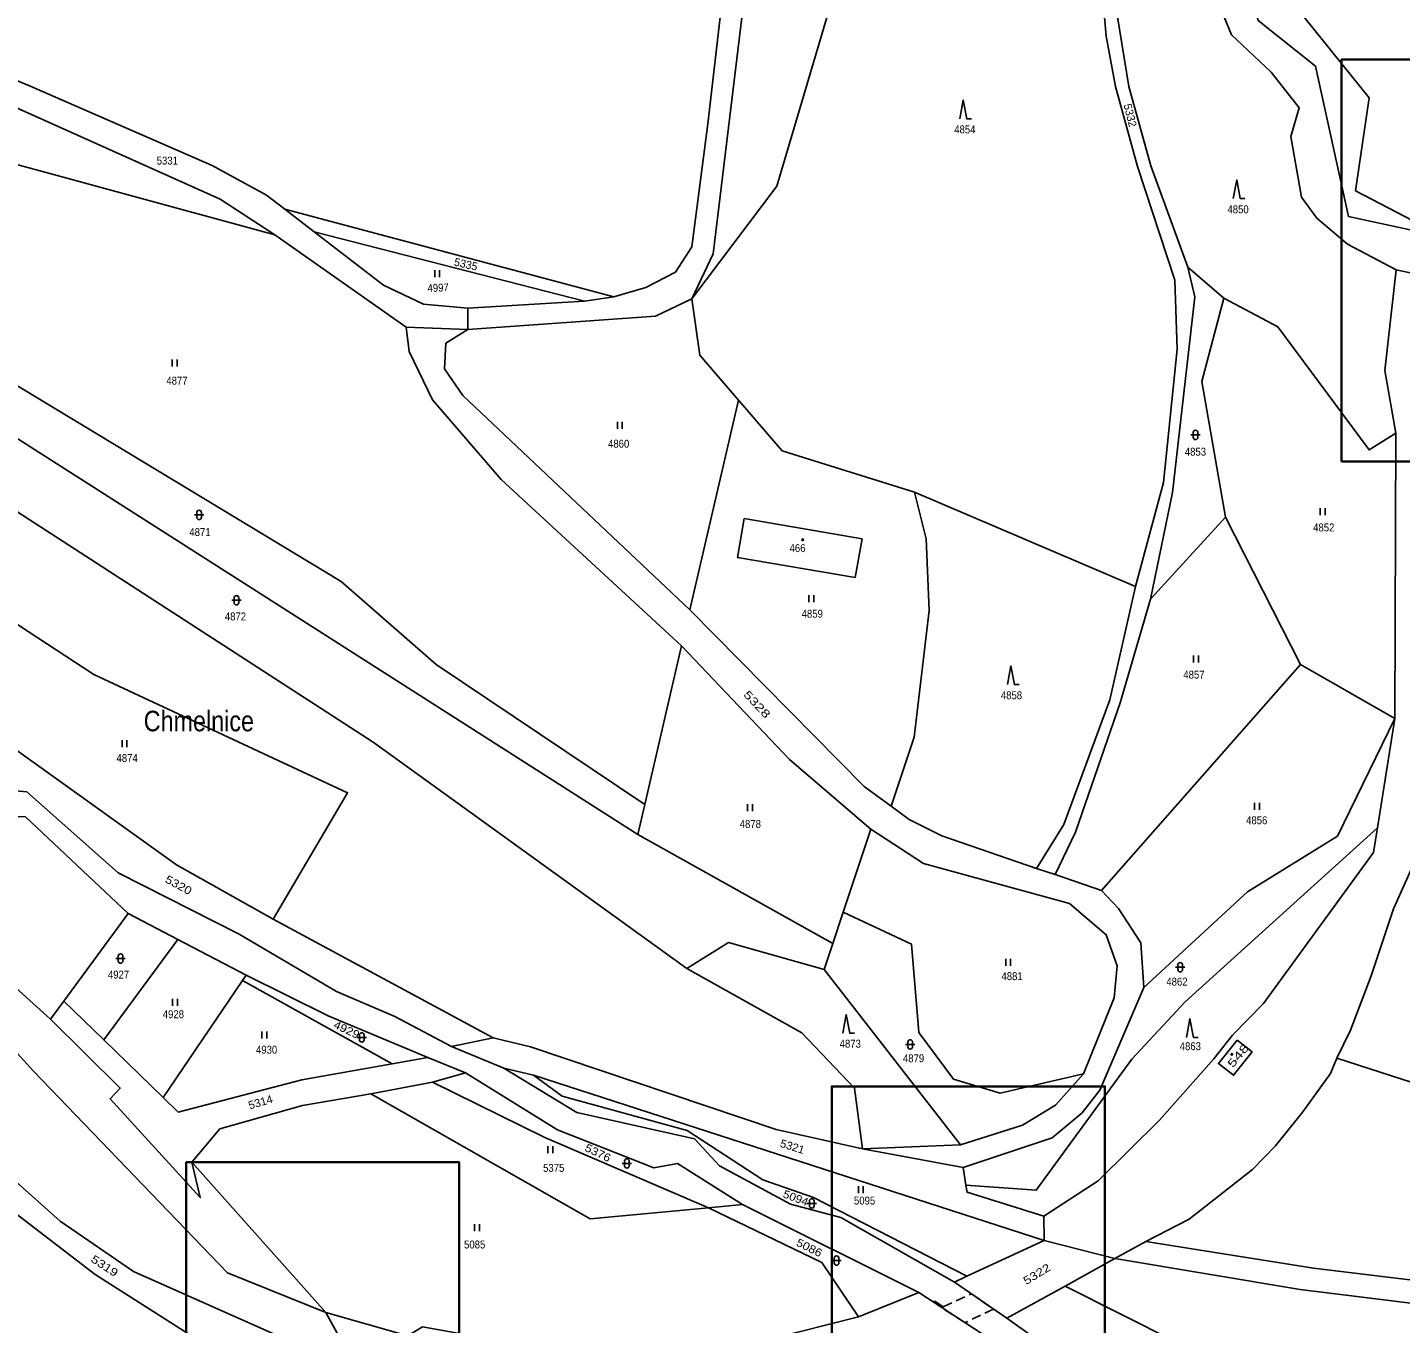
# Model space of a CAD drawing. Extents: x -665688 to -664583, y -1006118 to -1004927.
# Drawn here: x -665191.6 to -664897.5, y -1005454.1 to -1005176.4 of the extents above; entities that cross this region are included whole.
import ezdxf
from ezdxf.enums import TextEntityAlignment as Align

# ---------------------------------------------------------------- set-up
doc = ezdxf.new("R2010")
doc.units = 0
doc.header["$LTSCALE"] = 0.68
doc.linetypes.add('MEDIUM_DASHED', pattern=[4.5, 3, -1.5])
for name, color, linetype, lineweight in [('1', 7, 'Continuous', 25), ('25', 7, 'Continuous', 25), ('27', 7, 'MEDIUM_DASHED', 25), ('55', 7, 'Continuous', 35)]:
    doc.layers.add(name, color=color, linetype=linetype, lineweight=lineweight)
for name, color, linetype in [('15', 7, 'Continuous'), ('18', 7, 'Continuous'), ('19', 7, 'Continuous')]:
    doc.layers.add(name, color=color, linetype=linetype)

msp = doc.modelspace()

# ---------------------------------------------------------------- linework, layer by layer
at = {"layer": '1'}
for p, q in [((-665097.3, -1005241.05), (-665097.26, -1005236.54)), ((-665072.31, -1005234.98), (-665097.26, -1005236.54)), ((-665097.3, -1005241.05), (-665110.5, -1005240.56)), ((-664898.65, -1005324.46), (-664898.46, -1005263.33)), ((-664918.88, -1005312.89), (-664898.65, -1005324.46)), ((-664898.65, -1005324.46), (-664902.37, -1005347.86)), ((-664971.46, -1005357.88), (-664975.48, -1005356.59)), ((-665170.08, -1005366.25), (-665159.4, -1005371.83)), ((-665159.4, -1005371.83), (-665144.78, -1005379.46)), ((-665019.11, -1005372.67), (-665020.96, -1005378.24)), ((-665091.86, -1005392.84), (-665100.81, -1005394.75)), ((-665089.55, -1005399.37), (-665100.81, -1005394.75)), ((-665105.89, -1005397.05), (-665097.79, -1005400.37)), ((-665089.55, -1005399.37), (-665083.2, -1005400.84)), ((-665118.08, -1005404.88), (-665104.85, -1005402.34)), ((-664991.18, -1005420.63), (-665012.73, -1005416.63)), ((-665038.41, -1005428.56), (-665000.67, -1005447.45)), ((-664969.3, -1005446.1), (-664958.68, -1005440.16)), ((-664981.8, -1005452.97), (-664993.04, -1005445.2)), ((-664981.8, -1005452.97), (-664969.3, -1005446.1)), ((-665000.67, -1005447.45), (-665013.61, -1005452.67)), ((-665000.67, -1005447.45), (-664985.67, -1005457.24))]:
    msp.add_line(p, q, dxfattribs=at)
for points in [[(-664895.39, -1005219.73), (-664908.63, -1005216.84), (-664915.67, -1005184.63), (-664927.97, -1005174.84), (-664931.29, -1005161.96), (-664923.13, -1005157.75), (-664909.4, -1005145.58), (-664903.94, -1005133.92), (-664903.15, -1005127.85), (-664912.19, -1005084.06), (-664891.68, -1005067.49), (-664871.95, -1005045.77), (-664858.98, -1005033.99), (-664851.57, -1005033.48)], [(-664894.9, -1005217.74), (-664907.14, -1005211.36), (-664904.2, -1005191.46), (-664923.77, -1005167.11), (-664902.42, -1005142.29), (-664899.45, -1005128.56), (-664907.27, -1005091.69), (-664905.43, -1005083.63), (-664892.51, -1005077.23), (-664870.34, -1005046.85), (-664858.99, -1005037.17), (-664850.64, -1005036.62)], [(-665136.5, -1005215.33), (-665140.44, -1005212.3), (-665152.07, -1005205.93), (-665191.17, -1005188.9), (-665218.73, -1005177.39), (-665216.13, -1005170.52), (-665206.49, -1005145), (-665182.51, -1005081.53)], [(-665049.31, -1005234.5), (-665044.7, -1005224.87), (-665033.98, -1005136.54), (-665026.72, -1005106.52)], [(-665001.26, -1005109.58), (-665031.11, -1005210.37), (-665049.31, -1005234.5)], [(-664968.96, -1005115.26), (-664961.42, -1005140.2), (-664960.58, -1005145.04), (-664961.76, -1005164.25), (-664960.54, -1005178.21), (-664958.55, -1005188.98), (-664953.84, -1005206.17), (-664945.82, -1005230.5), (-664945.31, -1005245.28), (-664948.24, -1005273.87), (-664954.26, -1005296.16), (-665001.62, -1005275.92)], [(-665035.77, -1005123.25), (-665038.71, -1005135.19), (-665045.89, -1005196.99), (-665049.31, -1005223.37), (-665052.82, -1005228.77), (-665059.13, -1005232.1), (-665065.99, -1005234.1)], [(-664943, -1005227.75), (-664950.93, -1005206.04), (-664955.68, -1005188.99), (-664958.69, -1005170.55), (-664939.22, -1005164.33)], [(-664939.22, -1005164.33), (-664933.7, -1005177.92), (-664925.15, -1005185.97), (-664919.15, -1005193.6), (-664920.98, -1005199.71), (-664918.67, -1005212.71), (-664915.42, -1005217.25), (-664908.82, -1005222.82), (-664898.36, -1005228.3)], [(-665240.86, -1005177.51), (-665205.31, -1005188.54), (-665150.34, -1005213.14), (-665138.6, -1005220.79)], [(-665059.37, -1005342.9), (-665104.09, -1005312.9), (-665124.43, -1005295.1), (-665225.03, -1005234.3), (-665246.42, -1005229.05), (-665242.48, -1005192.49)], [(-665242.48, -1005192.49), (-665138.6, -1005220.79), (-665110.5, -1005240.56)], [(-665399.75, -1005208.35), (-665376.11, -1005222.26), (-665358.6, -1005232.91), (-665344.4, -1005243.08), (-665327.83, -1005258.99), (-665299.41, -1005297.42), (-665287.03, -1005311.31), (-665268.55, -1005328.24), (-665251.87, -1005341.72), (-665211.4, -1005376.84), (-665190.33, -1005399.99), (-665148.79, -1005443.19), (-665127.68, -1005451.74), (-665121.7, -1005462.65), (-665134.58, -1005458.21)], [(-665050.35, -1005378.04), (-665117.56, -1005329.51), (-665248.06, -1005245.09), (-665261.76, -1005239.56), (-665293.79, -1005218.72), (-665304.45, -1005209.39)], [(-665097.26, -1005236.54), (-665106.75, -1005235.64), (-665115.37, -1005231.58), (-665130.24, -1005220.14)], [(-664951.06, -1005298.9), (-664946.29, -1005275.99), (-664941.51, -1005234.09), (-664943, -1005227.75)], [(-664898.46, -1005263.33), (-664904.2, -1005266.89), (-664923.76, -1005240.51), (-664935.35, -1005234.38), (-664943, -1005227.75)], [(-664898.36, -1005228.3), (-664900.84, -1005249.89), (-664898.46, -1005263.33)], [(-664898.36, -1005228.3), (-664873.52, -1005233.6), (-664874.22, -1005299.23)], [(-665097.3, -1005241.05), (-665057.09, -1005238.2), (-665049.31, -1005234.5)], [(-665049.31, -1005234.5), (-665047.61, -1005246.59), (-665039.32, -1005256.22), (-665049.72, -1005301.17)], [(-664934.98, -1005281.28), (-664940.03, -1005252.24), (-664935.35, -1005234.38)], [(-665247.28, -1005237.07), (-665218.64, -1005248.65), (-665060.85, -1005349.31)], [(-665110.5, -1005240.56), (-665109.84, -1005245.77), (-665104.86, -1005256.16), (-665090.12, -1005273.19), (-665051.5, -1005308.87), (-665059.37, -1005342.9)], [(-665049.72, -1005301.17), (-665098.35, -1005255.21), (-665102.3, -1005249.51), (-665102, -1005243.98), (-665097.3, -1005241.05)], [(-665001.62, -1005275.92), (-665029.94, -1005267.11), (-665039.32, -1005256.22)], [(-665001.62, -1005275.92), (-664999.1, -1005285.91), (-664998.44, -1005301.31), (-665001.69, -1005328.42), (-665006.62, -1005343.23)], [(-665186.72, -1005388.88), (-665231.73, -1005348.14), (-665247.24, -1005335.03), (-665262.9, -1005322.2), (-665284.22, -1005302.33), (-665295.64, -1005288.54), (-665288.78, -1005281.42)], [(-665288.78, -1005281.42), (-665278.12, -1005293.76), (-665254.75, -1005298.72), (-665246.23, -1005320.3), (-665241.95, -1005328.41), (-665229.65, -1005333.27), (-665213.43, -1005330.83), (-665203.9, -1005345.02), (-665192.06, -1005345.49), (-665170.08, -1005366.25)], [(-664934.98, -1005281.28), (-664918.88, -1005312.89), (-664961.49, -1005361.3), (-664971.46, -1005357.88)], [(-664971.46, -1005357.88), (-664967.09, -1005348.78), (-664957.49, -1005321.11), (-664951.06, -1005298.9), (-664934.98, -1005281.28)], [(-664975.48, -1005356.59), (-664969.6, -1005347.14), (-664959.71, -1005320.47), (-664954.26, -1005296.16)], [(-665139.02, -1005367.43), (-665159.72, -1005355.83), (-665207.38, -1005321.62), (-665218.42, -1005320.08), (-665199.64, -1005300.53)], [(-665199.64, -1005300.53), (-665177.42, -1005315.04), (-665123.06, -1005340.35), (-665139.02, -1005367.43)], [(-665006.62, -1005343.23), (-665012.38, -1005338.99), (-665049.72, -1005301.17)], [(-665051.5, -1005308.87), (-665028.39, -1005333.21), (-665010.97, -1005348.18), (-665016.87, -1005365.92), (-665019.11, -1005372.67), (-665060.85, -1005349.31), (-665059.37, -1005342.9)], [(-664911.11, -1005397.23), (-664908.16, -1005391.22), (-664903.76, -1005379.6), (-664898.99, -1005365.23), (-664880.44, -1005324.02), (-664875.64, -1005308.45)], [(-665100.81, -1005394.75), (-665112.89, -1005388.29), (-665125.42, -1005382.92), (-665146.27, -1005370.65), (-665172.18, -1005357.52), (-665191.77, -1005340.12), (-665198.15, -1005339.57), (-665203.62, -1005332.13), (-665212.87, -1005325.35), (-665222.91, -1005324.76)], [(-664898.65, -1005324.46), (-664910.98, -1005349.63), (-664930.26, -1005361.6), (-664952.48, -1005382.07)], [(-664975.48, -1005356.59), (-664995.7, -1005349.58), (-665002.76, -1005346.07), (-665006.62, -1005343.23)], [(-665010.97, -1005348.18), (-664999.64, -1005355.54), (-664968.37, -1005364.11), (-664960.56, -1005370.78), (-664958.18, -1005377.42), (-664958.78, -1005384.32), (-664965.36, -1005400.61)], [(-664902.37, -1005347.86), (-664943.61, -1005385.12), (-664955.01, -1005397.41), (-664975.49, -1005425.51), (-664990.58, -1005424.46), (-664991.18, -1005420.63)], [(-664902.37, -1005347.86), (-664903.22, -1005353.17), (-664926.83, -1005385.53), (-664933.44, -1005392.32), (-664937.47, -1005397.34), (-664949.13, -1005410.53), (-664962.23, -1005423.51), (-664973.85, -1005431.1)], [(-664952.48, -1005382.07), (-664953.08, -1005372.54), (-664957.87, -1005365.15), (-664961.49, -1005361.3)], [(-665170.08, -1005366.25), (-665183.86, -1005384.99), (-665186.72, -1005388.88)], [(-665016.87, -1005365.92), (-665002.22, -1005372.83), (-665000.64, -1005391.69), (-664993.21, -1005401.74), (-664983.24, -1005404.71), (-664965.36, -1005400.61)], [(-665012.73, -1005416.63), (-665031.21, -1005412.54), (-665083.85, -1005394.79), (-665091.86, -1005392.84), (-665139.02, -1005367.43)], [(-665159.4, -1005371.83), (-665175.28, -1005393.3), (-665183.86, -1005384.99)], [(-665020.96, -1005378.24), (-665041.41, -1005372.47), (-665050.35, -1005378.04)], [(-664847.73, -1005373.11), (-664853.38, -1005372.05), (-664890.31, -1005403.96), (-664911.11, -1005397.23)], [(-665050.35, -1005378.04), (-665025.75, -1005391.78), (-665014.41, -1005403.65), (-665012.73, -1005416.63)], [(-665020.96, -1005378.24), (-664991.72, -1005415.78), (-665012.73, -1005416.63)], [(-665145.53, -1005380.57), (-665162.55, -1005405.66), (-665175.28, -1005393.3)], [(-665105.89, -1005397.05), (-665113.52, -1005398.42), (-665145.53, -1005380.57), (-665144.78, -1005379.46)], [(-665144.78, -1005379.46), (-665127.19, -1005388.15), (-665105.89, -1005397.05)], [(-664991.18, -1005420.63), (-664972.09, -1005414.33), (-664965.7, -1005408.91), (-664961.91, -1005404.06), (-664952.48, -1005382.07)], [(-665156.4, -1005419.5), (-665154.61, -1005427.1), (-665173.94, -1005405.95), (-665171.75, -1005403.64), (-665186.72, -1005388.88)], [(-665113.52, -1005398.42), (-665132.82, -1005401.87), (-665159.35, -1005408.77), (-665162.55, -1005405.66)], [(-664993.04, -1005445.2), (-665017.35, -1005431.35), (-665028.16, -1005428.51), (-665043.37, -1005420.31), (-665048.74, -1005414.54), (-665073.92, -1005408.87), (-665089.55, -1005399.37)], [(-664911.11, -1005397.23), (-664912.46, -1005400.49), (-664918.41, -1005408.69), (-664924.27, -1005416.02), (-664929.2, -1005421.1), (-664942.75, -1005431.69), (-664952, -1005436.49), (-664958.68, -1005440.16), (-664973.84, -1005436.33), (-664973.85, -1005431.1)], [(-665045.75, -1005429.26), (-665080.8, -1005414.25), (-665104.85, -1005402.34), (-665097.79, -1005400.37)], [(-665097.79, -1005400.37), (-665078.05, -1005412.57), (-665057.45, -1005420.7), (-665052.37, -1005419.81), (-665038.41, -1005428.56)], [(-665083.2, -1005400.84), (-664973.84, -1005436.33), (-664990.35, -1005443.96)], [(-665083.2, -1005400.84), (-665077.11, -1005405.36), (-665050.32, -1005412.75), (-665034.07, -1005423.33), (-665023.2, -1005427.08), (-664990.35, -1005443.96), (-664993.04, -1005445.2)], [(-664965.36, -1005400.61), (-664971.4, -1005407.3), (-664978.47, -1005411.61), (-664991.72, -1005415.78)], [(-665156.4, -1005419.5), (-665150.41, -1005412.37), (-665132.72, -1005407.37), (-665118.08, -1005404.88)], [(-665118.08, -1005404.88), (-665071.08, -1005431.67), (-665045.75, -1005429.26)], [(-665136.29, -1005477.24), (-665150.22, -1005460.69), (-665177.15, -1005443.61), (-665221.19, -1005409.78), (-665210.58, -1005407.96)], [(-665210.58, -1005407.96), (-665198.15, -1005420.12), (-665184.6, -1005432.15), (-665168.91, -1005442.94), (-665134.58, -1005458.21), (-665131.02, -1005461.53)], [(-665013.61, -1005452.67), (-665032.2, -1005457.35), (-665049.69, -1005459.74), (-665076.88, -1005460.21), (-665107.01, -1005454.78), (-665110.17, -1005456.74), (-665127.68, -1005451.74), (-665156.4, -1005419.5)], [(-664973.85, -1005431.1), (-664990.34, -1005425.94), (-664990.58, -1005424.46)], [(-665013.61, -1005452.67), (-665021.41, -1005441.03), (-665045.75, -1005429.26), (-665038.41, -1005428.56)], [(-664812.89, -1005451.45), (-664818.34, -1005452.22), (-664821.75, -1005452.39), (-664832, -1005452.23), (-664844.79, -1005450.86), (-664916.08, -1005442.22), (-664952, -1005436.49)], [(-664958.68, -1005440.16), (-664918.99, -1005446.77), (-664835.18, -1005457.14), (-664824.19, -1005457.34), (-664809.08, -1005455.92), (-664802.4, -1005456.42), (-664792.15, -1005466.99), (-664796.78, -1005468.06), (-664803.23, -1005465.97)], [(-664969.3, -1005446.1), (-664945.43, -1005458.11), (-664870.22, -1005475.95), (-664843.38, -1005478.52), (-664808.84, -1005489.57), (-664807.3, -1005497.72)], [(-664807.3, -1005497.72), (-664823.52, -1005498.49), (-664831.43, -1005490.72), (-664845.63, -1005484.35), (-664861.39, -1005491.91), (-664864, -1005488.5), (-664869.71, -1005485.89), (-664886.34, -1005486.35), (-664888.54, -1005481.42), (-664895.39, -1005478.51), (-664911.15, -1005478.85), (-664917.14, -1005475.22), (-664920.29, -1005468.16), (-664939.44, -1005469.7), (-664948.5, -1005477.86), (-664952.19, -1005476.3), (-664954.45, -1005466.18), (-664962.99, -1005461.77), (-664976.12, -1005457.02), (-664981.8, -1005452.97)]]:
    msp.add_lwpolyline(points, dxfattribs=at)
for points in [[(-665136.5, -1005215.33), (-665065.99, -1005234.1), (-665072.31, -1005234.98), (-665130.24, -1005220.14)], [(-665038.07, -1005281.58), (-665039.49, -1005289.96), (-665014.27, -1005294.21), (-665012.82, -1005285.97)], [(-664932.47, -1005393.36), (-664936.49, -1005398.39), (-664933.24, -1005400.88), (-664929.25, -1005395.88)]]:
    msp.add_lwpolyline(points, close=True, dxfattribs=at)
at = {"layer": '25'}
for p, q in [((-665104.357, -1005229.855), (-665104.357, -1005228.355)), ((-665103.323, -1005229.855), (-665103.323, -1005228.355)), ((-665160.627, -1005249.025), (-665160.627, -1005247.525)), ((-665159.593, -1005249.025), (-665159.593, -1005247.525)), ((-665065.237, -1005262.335), (-665065.237, -1005260.835)), ((-665064.203, -1005262.335), (-665064.203, -1005260.835)), ((-664942.37, -1005263.66), (-664940.37, -1005263.66)), ((-664941.87, -1005264.16), (-664941.87, -1005263.16)), ((-664940.87, -1005263.16), (-664940.87, -1005264.16)), ((-665155.87, -1005280.82), (-665153.87, -1005280.82)), ((-665155.37, -1005281.32), (-665155.37, -1005280.32)), ((-665154.37, -1005280.32), (-665154.37, -1005281.32)), ((-664914.667, -1005280.895), (-664914.667, -1005279.395)), ((-664913.633, -1005280.895), (-664913.633, -1005279.395)), ((-665147.86, -1005299.1), (-665145.86, -1005299.1)), ((-665147.36, -1005299.6), (-665147.36, -1005298.6)), ((-665146.36, -1005298.6), (-665146.36, -1005299.6)), ((-665024.207, -1005299.535), (-665024.207, -1005298.035)), ((-665023.173, -1005299.535), (-665023.173, -1005298.035)), ((-664941.797, -1005312.425), (-664941.797, -1005310.925)), ((-664940.763, -1005312.425), (-664940.763, -1005310.925)), ((-665171.367, -1005330.615), (-665171.367, -1005329.115)), ((-665170.333, -1005330.615), (-665170.333, -1005329.115)), ((-665037.357, -1005344.265), (-665037.357, -1005342.765)), ((-665036.323, -1005344.265), (-665036.323, -1005342.765)), ((-664928.727, -1005344.015), (-664928.727, -1005342.515)), ((-664927.693, -1005344.015), (-664927.693, -1005342.515)), ((-665172.69, -1005375.88), (-665170.69, -1005375.88)), ((-665172.19, -1005376.38), (-665172.19, -1005375.38)), ((-665171.19, -1005375.38), (-665171.19, -1005376.38)), ((-664982.047, -1005377.465), (-664982.047, -1005375.965)), ((-664981.013, -1005377.465), (-664981.013, -1005375.965)), ((-664945.64, -1005377.74), (-664943.64, -1005377.74)), ((-664945.14, -1005378.24), (-664945.14, -1005377.24)), ((-664944.14, -1005377.24), (-664944.14, -1005378.24)), ((-665160.547, -1005386.045), (-665160.547, -1005384.545)), ((-665159.513, -1005386.045), (-665159.513, -1005384.545)), ((-665141.387, -1005393.005), (-665141.387, -1005391.505)), ((-665140.353, -1005393.005), (-665140.353, -1005391.505)), ((-665121.01, -1005392.77), (-665119.01, -1005392.77)), ((-665120.51, -1005393.27), (-665120.51, -1005392.27)), ((-665119.51, -1005392.27), (-665119.51, -1005393.27)), ((-665003.51, -1005394.29), (-665001.51, -1005394.29)), ((-665003.01, -1005394.79), (-665003.01, -1005393.79)), ((-665002.01, -1005393.79), (-665002.01, -1005394.79)), ((-665080.117, -1005417.555), (-665080.117, -1005416.055)), ((-665079.083, -1005417.555), (-665079.083, -1005416.055)), ((-665064.2, -1005419.79), (-665062.2, -1005419.79)), ((-665063.7, -1005420.29), (-665063.7, -1005419.29)), ((-665062.7, -1005419.29), (-665062.7, -1005420.29)), ((-665013.617, -1005426.155), (-665013.617, -1005424.655)), ((-665012.583, -1005426.155), (-665012.583, -1005424.655)), ((-665024.59, -1005428.36), (-665022.59, -1005428.36)), ((-665024.09, -1005428.86), (-665024.09, -1005427.86)), ((-665023.09, -1005427.86), (-665023.09, -1005428.86)), ((-665095.847, -1005434.315), (-665095.847, -1005432.815)), ((-665094.813, -1005434.315), (-665094.813, -1005432.815)), ((-665019.29, -1005440.6), (-665017.29, -1005440.6)), ((-665018.79, -1005441.1), (-665018.79, -1005440.1)), ((-665017.79, -1005440.1), (-665017.79, -1005441.1))]:
    msp.add_line(p, q, dxfattribs=at)
for points in [[(-664991.91, -1005195.94), (-664991.16, -1005191.94), (-664990.41, -1005195.94), (-664989.41, -1005195.94)], [(-664933.3, -1005213.02), (-664932.55, -1005209.02), (-664931.8, -1005213.02), (-664930.8, -1005213.02)], [(-664981.68, -1005317.16), (-664980.93, -1005313.16), (-664980.18, -1005317.16), (-664979.18, -1005317.16)], [(-665016.95, -1005391.9), (-665016.2, -1005387.9), (-665015.45, -1005391.9), (-665014.45, -1005391.9)], [(-664943.32, -1005392.79), (-664942.57, -1005388.79), (-664941.82, -1005392.79), (-664940.82, -1005392.79)]]:
    msp.add_lwpolyline(points, dxfattribs=at)
for centre in [(-665025.56, -1005286.14), (-664933.6, -1005396.42)]:
    msp.add_circle(centre, 0.175, dxfattribs=at)
for centre, start, end in [((-664941.37, -1005263.16), 0.101, 180.00143), ((-664941.37, -1005264.16), 180.10243, 0.00286), ((-665154.87, -1005280.32), 0.101, 180.00143), ((-665154.87, -1005281.32), 180.10243, 0.00286), ((-665146.86, -1005298.6), 0.101, 180.00143), ((-665146.86, -1005299.6), 180.10243, 0.00286), ((-665171.69, -1005375.38), 0.101, 180.00143), ((-665171.69, -1005376.38), 180.10243, 0.00286), ((-664944.64, -1005377.24), 0.101, 180.00143), ((-664944.64, -1005378.24), 180.10243, 0.00286), ((-665120.01, -1005392.27), 0.101, 180.00143), ((-665120.01, -1005393.27), 180.10243, 0.00286), ((-665002.51, -1005393.79), 0.101, 180.00143), ((-665002.51, -1005394.79), 180.10243, 0.00286), ((-665063.2, -1005419.29), 0.101, 180.00143), ((-665063.2, -1005420.29), 180.10243, 0.00286), ((-665023.59, -1005427.86), 0.101, 180.00143), ((-665023.59, -1005428.86), 180.10243, 0.00286), ((-665018.29, -1005440.1), 0.101, 180.00143), ((-665018.29, -1005441.1), 180.10243, 0.00286)]:
    msp.add_arc(centre, 0.5, start, end, dxfattribs=at)
at = {"layer": '27'}
msp.add_lwpolyline([(-664997.63, -1005449.44), (-664997.23, -1005449.28), (-664995.44, -1005450.48), (-664989.37, -1005447.74), (-664984.65, -1005451), (-664990.78, -1005453.9)], close=True, dxfattribs=at)
at = {"layer": '55'}
for points in [[(-664910.13, -1005269.36), (-664910.13, -1005183.26), (-664851.63, -1005183.26), (-664851.63, -1005269.36)], [(-665019.3, -1005489.36), (-665019.3, -1005403.26), (-664960.8, -1005403.26), (-664960.8, -1005489.36)], [(-665157.63, -1005505.61), (-665157.63, -1005419.51), (-665099.13, -1005419.51), (-665099.13, -1005505.61)]]:
    msp.add_lwpolyline(points, close=True, dxfattribs=at)

# ---------------------------------------------------------------- texts
at = {"layer": '15', "width": 0.85}
msp.add_text('Chmelnice', height=4.4, dxfattribs=at).set_placement((-665154.91, -1005327.18), align=Align.CENTER)
at = {"layer": '18'}
for s, rotation, p in [('5332', 284.302, (-664956.194, -1005195.3945)), ('5335', 347.203, (-665097.8878, -1005227.9241))]:
    msp.add_text(s, height=1.7, rotation=rotation, dxfattribs=at).set_placement(p, align=Align.CENTER)
at = {"layer": '18', "width": 0.9}
for s, p in [('4854', (-664990.7995, -1005199.06)), ('5331', (-665161.6695, -1005205.74)), ('4850', (-664932.2695, -1005216.18)), ('4877', (-665159.5995, -1005252.89)), ('4860', (-665064.9695, -1005266.41)), ('4853', (-664941.3995, -1005268.12)), ('4871', (-665154.6695, -1005285.34)), ('4852', (-664913.9095, -1005284.35)), ('4872', (-665147.0695, -1005303.42)), ('4859', (-665023.4895, -1005302.84)), ('4857', (-664941.7195, -1005315.89)), ('4858', (-664980.8095, -1005320.31)), ('4874', (-665170.2795, -1005333.76)), ('4878', (-665036.7595, -1005347.89)), ('4856', (-664928.2695, -1005347.1)), ('4927', (-665172.1195, -1005380.17)), ('4881', (-664980.6795, -1005380.5)), ('4862', (-664945.3595, -1005381.68)), ('4928', (-665160.3695, -1005388.66)), ('4873', (-665015.3495, -1005394.97)), ('4930', (-665140.3995, -1005396.26)), ('4879', (-665001.7895, -1005398.1)), ('4863', (-664942.4895, -1005395.51)), ('5375', (-665078.8795, -1005421.58)), ('5095', (-665012.2795, -1005428.59)), ('5085', (-665095.8195, -1005438))]:
    msp.add_text(s, height=1.7, dxfattribs=at).set_placement(p, align=Align.CENTER)
at = {"layer": '18'}
for s, rotation, width, p in [('4997', 1.7, 0.9, (-665103.6317, -1005232.9815)), ('5328', 313.402, 1.4, (-665035.9492, -1005322.003)), ('5320', 331.703, 1.2, (-665159.6544, -1005360.8756)), ('4929', 334.703, 1.15, (-665123.6157, -1005391.8805)), ('5314', 16.6, 1.05, (-665141.4698, -1005407.466)), ('5376', 334.303, 1.15, (-665069.7831, -1005418.2691)), ('5321', 342.803, 1.05, (-665027.9908, -1005416.9805)), ('5094', 339.603, 1.1, (-665027.3242, -1005427.9694)), ('5086', 333.403, 1.15, (-665024.5066, -1005438.5971)), ('5319', 327.003, 1.25, (-665175.5624, -1005442.4438)), ('5322', 31.5, 1.25, (-664974.9351, -1005444.2067))]:
    msp.add_text(s, height=1.7, rotation=rotation, dxfattribs=dict(at, width=width)).set_placement(p, align=Align.CENTER)
at = {"layer": '19', "width": 0.9}
msp.add_text('466', height=1.7, dxfattribs=at).set_placement((-665028.36, -1005288.78))
at = {"layer": '19', "width": 1.5}
msp.add_text('548', height=1.7, rotation=50.2, dxfattribs=at).set_placement((-664933.415, -1005399.419))

doc.saveas('drawing.dxf')
